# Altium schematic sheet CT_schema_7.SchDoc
size 277 x 170 mm
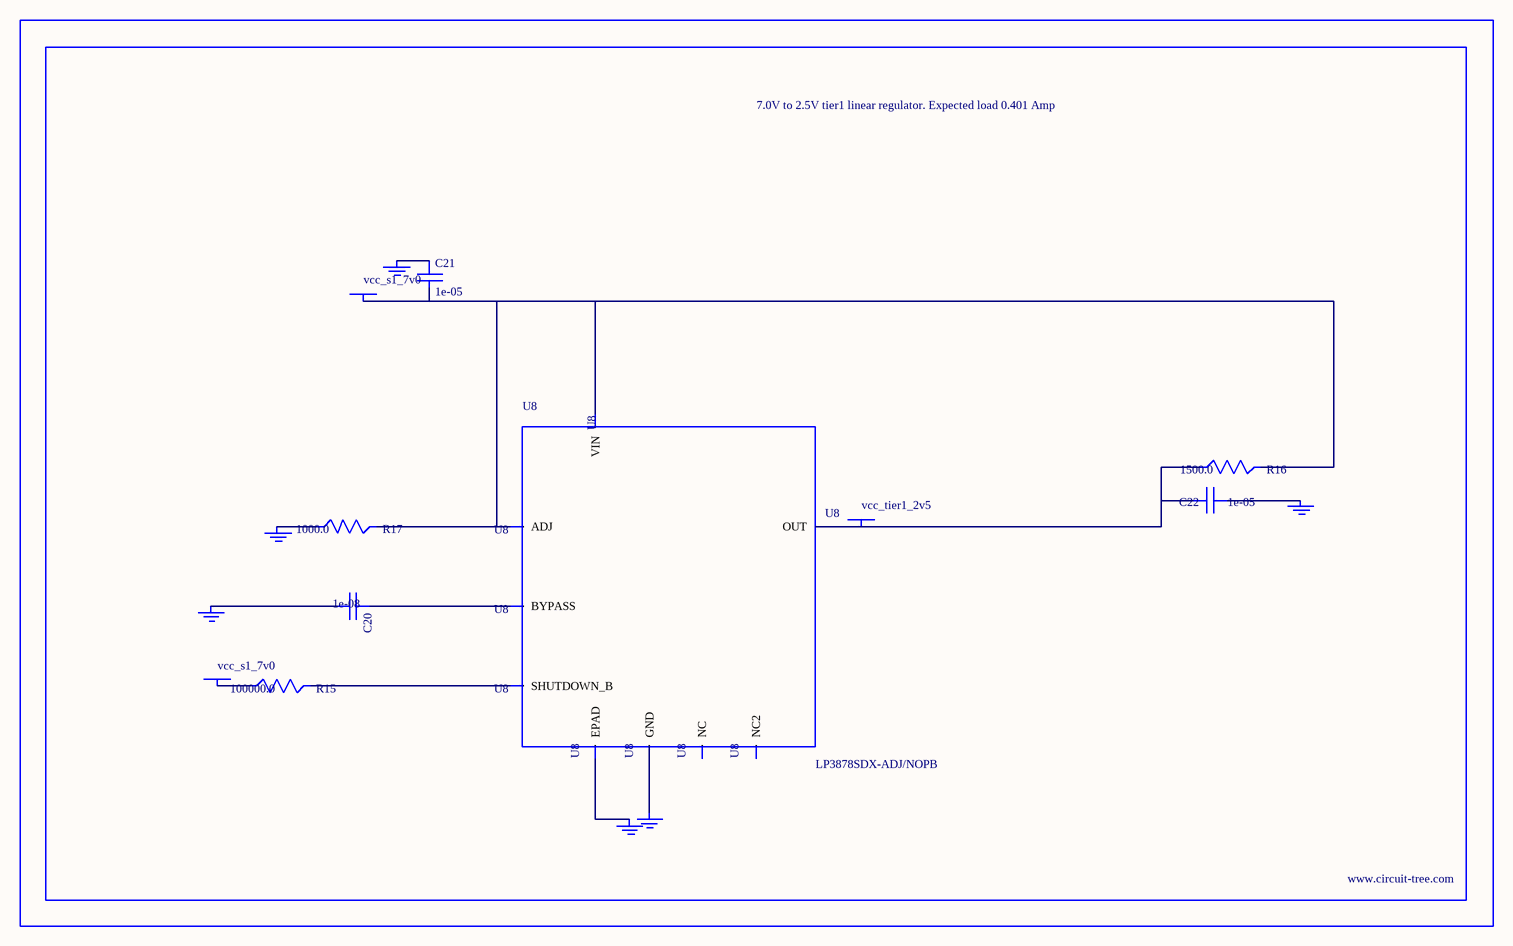
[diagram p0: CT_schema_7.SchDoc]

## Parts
BORDER6  (no value)
C20  1e-08  [C0402]
C21  1e-05  [C1206]
C22  1e-05  [C1210]
GND_INSTANCE_6_0  (no value)
GND_INSTANCE_6_1  (no value)
GND_INSTANCE_6_2  (no value)
GND_INSTANCE_6_3  (no value)
GND_INSTANCE_6_4  (no value)
GND_INSTANCE_6_5  (no value)
POWER_INSTANCE_6_0  vcc_s1_7v0
POWER_INSTANCE_6_1  vcc_s1_7v0
POWER_INSTANCE_6_2  vcc_tier1_2v5
R15  100000.0  [R0603]
R16  1500.0  [R0603]
R17  1000.0  [R0603]
U8  LP3878SDX-ADJ/NOPB  [WSON-8]

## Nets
NetC20_1: C20.1 U8.1(BYPASS)
NetC20_2: C20.2 GND_INSTANCE_6_0.0(GND)
NetC21_1: C21.1 GND_INSTANCE_6_1.0(GND)
NetC21_2: C21.2 POWER_INSTANCE_6_0.0(PWR) R16.2 R17.2 U8.4(VIN) U8.6(ADJ)
NetC22_1: C22.1 GND_INSTANCE_6_2.0(GND)
NetC22_2: C22.2 POWER_INSTANCE_6_2.0(PWR) R16.1 U8.5(OUT)
NetGND_INSTANCE_6_3_0: GND_INSTANCE_6_3.0(GND) R17.1
NetGND_INSTANCE_6_4_0: GND_INSTANCE_6_4.0(GND) U8.PAD(EPAD)
NetGND_INSTANCE_6_5_0: GND_INSTANCE_6_5.0(GND) U8.3(GND)
NetPOWER_INSTANCE_6_1_0: POWER_INSTANCE_6_1.0(PWR) R15.1
NetR15_2: R15.2 U8.8(SHUTDOWN_B)

Not connected (* = marked no-connect by the designer): U8 2(NC) 7(NC2)

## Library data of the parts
BORDER6 = BORDER_PAGE6
C20 = C0402C103K3RAC
C21 = C1206C106K3RACTU
C22 = GRM32DR61E106MA12L
GND_INSTANCE_6_0-GND_INSTANCE_6_5 = GND
POWER_INSTANCE_6_0-POWER_INSTANCE_6_2 = PWR
R15 = RC0603JR-07100KL
R16 = RC0603JR-071K5L
R17 = RC0603JR-071KL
